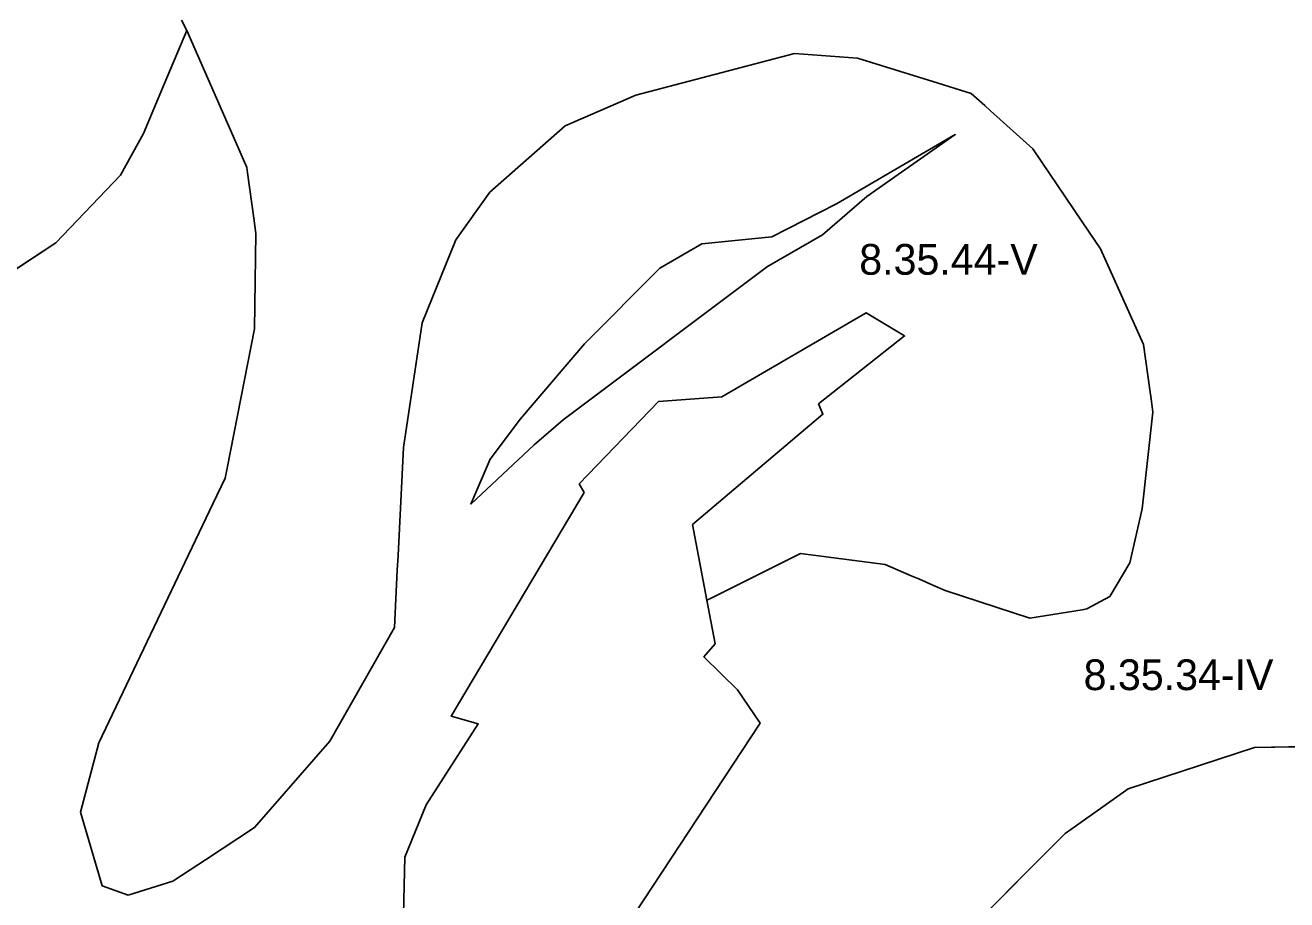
# Model space of a CAD drawing. Extents: x -547623 to -533936, y -1096714 to -1086523.
# Drawn here: x -544374 to -543964, y -1094794 to -1094509.8 of the extents above; entities that cross this region are included whole.
import ezdxf

# ---------------------------------------------------------------- set-up
doc = ezdxf.new("R2010")
doc.units = 0
doc.layers.add('Vrstva 27', color=7, linetype='Continuous')
doc.layers.add('Vrstva 28', color=7, linetype='Continuous')

msp = doc.modelspace()

# ---------------------------------------------------------------- linework, layer by layer
at = {"layer": 'Vrstva 28'}
for p, q in [((-544328.81, -1094529), (-544321.5, -1094511.5)), ((-544321.5, -1094511.5), (-544328.81, -1094529)), ((-544321.5, -1094511.5), (-544328.81, -1094529)), ((-544321.5, -1094511.5), (-544323.2, -1094508.1)), ((-544323.2, -1094508.1), (-544321.5, -1094511.5)), ((-544323.2, -1094508.1), (-544321.5, -1094511.5)), ((-544304.91, -1094549.36), (-544321.5, -1094511.5)), ((-544321.5, -1094511.5), (-544304.91, -1094549.36)), ((-544304.91, -1094549.36), (-544321.5, -1094511.5)), ((-544321.5, -1094511.5), (-544304.91, -1094549.36)), ((-544124, -1094519), (-544175.5, -1094532.5)), ((-544175.5, -1094532.5), (-544124, -1094519)), ((-544124, -1094519), (-544175.5, -1094532.5)), ((-544175.5, -1094532.5), (-544124, -1094519)), ((-544103.5, -1094520.5), (-544124, -1094519)), ((-544124, -1094519), (-544103.5, -1094520.5)), ((-544103.5, -1094520.5), (-544124, -1094519)), ((-544124, -1094519), (-544103.5, -1094520.5)), ((-544079.02, -1094528.11), (-544103.5, -1094520.5)), ((-544103.5, -1094520.5), (-544079.02, -1094528.11)), ((-544079.02, -1094528.11), (-544103.5, -1094520.5)), ((-544103.5, -1094520.5), (-544079.02, -1094528.11)), ((-544066.5, -1094532), (-544079.02, -1094528.11)), ((-544079.02, -1094528.11), (-544066.5, -1094532)), ((-544066.5, -1094532), (-544079.02, -1094528.11)), ((-544079.02, -1094528.11), (-544066.5, -1094532)), ((-544335.5, -1094545), (-544328.81, -1094529)), ((-544328.81, -1094529), (-544335.5, -1094545)), ((-544328.81, -1094529), (-544335.5, -1094545)), ((-544175.5, -1094532.5), (-544198.5, -1094542.5)), ((-544198.5, -1094542.5), (-544175.5, -1094532.5)), ((-544175.5, -1094532.5), (-544198.5, -1094542.5)), ((-544198.5, -1094542.5), (-544175.5, -1094532.5)), ((-544062.13, -1094535.93), (-544066.5, -1094532)), ((-544066.5, -1094532), (-544062.13, -1094535.93)), ((-544062.13, -1094535.93), (-544066.5, -1094532)), ((-544066.5, -1094532), (-544062.13, -1094535.93)), ((-544060.29, -1094537.59), (-544062.13, -1094535.93)), ((-544062.13, -1094535.93), (-544060.29, -1094537.59)), ((-544060.29, -1094537.59), (-544062.13, -1094535.93)), ((-544062.13, -1094535.93), (-544060.29, -1094537.59)), ((-544046.5, -1094550), (-544060.29, -1094537.59)), ((-544060.29, -1094537.59), (-544046.5, -1094550)), ((-544046.5, -1094550), (-544060.29, -1094537.59)), ((-544060.29, -1094537.59), (-544046.5, -1094550)), ((-544198.5, -1094542.5), (-544223, -1094564)), ((-544223, -1094564), (-544198.5, -1094542.5)), ((-544198.5, -1094542.5), (-544223, -1094564)), ((-544223, -1094564), (-544198.5, -1094542.5)), ((-544343, -1094558.5), (-544335.5, -1094545)), ((-544335.5, -1094545), (-544343, -1094558.5)), ((-544335.5, -1094545), (-544343, -1094558.5)), ((-544302, -1094556), (-544304.91, -1094549.36)), ((-544304.91, -1094549.36), (-544302, -1094556)), ((-544302, -1094556), (-544304.91, -1094549.36)), ((-544304.91, -1094549.36), (-544302, -1094556)), ((-544030.47, -1094573.68), (-544046.5, -1094550)), ((-544046.5, -1094550), (-544030.47, -1094573.68)), ((-544030.47, -1094573.68), (-544046.5, -1094550)), ((-544046.5, -1094550), (-544030.47, -1094573.68)), ((-544301.75, -1094557.82), (-544302, -1094556)), ((-544302, -1094556), (-544301.75, -1094557.82)), ((-544301.75, -1094557.82), (-544302, -1094556)), ((-544302, -1094556), (-544301.75, -1094557.82)), ((-544364, -1094580.5), (-544343, -1094558.5)), ((-544343, -1094558.5), (-544364, -1094580.5)), ((-544343, -1094558.5), (-544364, -1094580.5)), ((-544299.69, -1094572.52), (-544301.75, -1094557.82)), ((-544301.75, -1094557.82), (-544299.69, -1094572.52)), ((-544299.69, -1094572.52), (-544301.75, -1094557.82)), ((-544301.75, -1094557.82), (-544299.69, -1094572.52)), ((-544223, -1094564), (-544234, -1094579.5)), ((-544234, -1094579.5), (-544223, -1094564)), ((-544223, -1094564), (-544234, -1094579.5)), ((-544234, -1094579.5), (-544223, -1094564)), ((-544299, -1094577.5), (-544299.69, -1094572.52)), ((-544299.69, -1094572.52), (-544299, -1094577.5)), ((-544299, -1094577.5), (-544299.69, -1094572.52)), ((-544299.69, -1094572.52), (-544299, -1094577.5)), ((-544299.5, -1094608.5), (-544299, -1094577.5)), ((-544299, -1094577.5), (-544299.5, -1094608.5)), ((-544299.5, -1094608.5), (-544299, -1094577.5)), ((-544299, -1094577.5), (-544299.5, -1094608.5)), ((-544024.5, -1094582.5), (-544030.47, -1094573.68)), ((-544030.47, -1094573.68), (-544024.5, -1094582.5)), ((-544024.5, -1094582.5), (-544030.47, -1094573.68)), ((-544030.47, -1094573.68), (-544024.5, -1094582.5)), ((-544400.5, -1094604.5), (-544364, -1094580.5)), ((-544364, -1094580.5), (-544400.5, -1094604.5)), ((-544364, -1094580.5), (-544400.5, -1094604.5)), ((-544234, -1094579.5), (-544245, -1094606.5)), ((-544245, -1094606.5), (-544234, -1094579.5)), ((-544234, -1094579.5), (-544245, -1094606.5)), ((-544245, -1094606.5), (-544234, -1094579.5)), ((-544010.5, -1094613.5), (-544024.5, -1094582.5)), ((-544024.5, -1094582.5), (-544010.5, -1094613.5)), ((-544010.5, -1094613.5), (-544024.5, -1094582.5)), ((-544024.5, -1094582.5), (-544010.5, -1094613.5)), ((-544308.36, -1094653.71), (-544299.5, -1094608.5)), ((-544299.5, -1094608.5), (-544308.36, -1094653.71)), ((-544308.36, -1094653.71), (-544299.5, -1094608.5)), ((-544299.5, -1094608.5), (-544308.36, -1094653.71)), ((-544245, -1094606.5), (-544251, -1094647)), ((-544251, -1094647), (-544245, -1094606.5)), ((-544245, -1094606.5), (-544251, -1094647)), ((-544251, -1094647), (-544245, -1094606.5)), ((-544008.48, -1094628.3), (-544010.5, -1094613.5)), ((-544010.5, -1094613.5), (-544008.48, -1094628.3)), ((-544008.48, -1094628.3), (-544010.5, -1094613.5)), ((-544010.5, -1094613.5), (-544008.48, -1094628.3)), ((-544008.08, -1094631.23), (-544008.48, -1094628.3)), ((-544008.48, -1094628.3), (-544008.08, -1094631.23)), ((-544008.08, -1094631.23), (-544008.48, -1094628.3)), ((-544008.48, -1094628.3), (-544008.08, -1094631.23)), ((-544007.5, -1094635.5), (-544008.08, -1094631.23)), ((-544008.08, -1094631.23), (-544007.5, -1094635.5)), ((-544007.5, -1094635.5), (-544008.08, -1094631.23)), ((-544008.08, -1094631.23), (-544007.5, -1094635.5)), ((-544011, -1094667), (-544007.5, -1094635.5)), ((-544007.5, -1094635.5), (-544011, -1094667)), ((-544011, -1094667), (-544007.5, -1094635.5)), ((-544007.5, -1094635.5), (-544011, -1094667)), ((-544251, -1094647), (-544252.8, -1094682.13)), ((-544252.8, -1094682.13), (-544251, -1094647)), ((-544251, -1094647), (-544252.8, -1094682.13)), ((-544252.8, -1094682.13), (-544251, -1094647)), ((-544309, -1094657), (-544308.36, -1094653.71)), ((-544308.36, -1094653.71), (-544309, -1094657)), ((-544309, -1094657), (-544308.36, -1094653.71)), ((-544308.36, -1094653.71), (-544309, -1094657)), ((-544312.98, -1094665.36), (-544309, -1094657)), ((-544309, -1094657), (-544312.98, -1094665.36)), ((-544312.98, -1094665.36), (-544309, -1094657)), ((-544309, -1094657), (-544312.98, -1094665.36)), ((-544193.94, -1094658.82), (-544192.3, -1094661.6)), ((-544350, -1094743), (-544312.98, -1094665.36)), ((-544312.98, -1094665.36), (-544350, -1094743)), ((-544350, -1094743), (-544312.98, -1094665.36)), ((-544312.98, -1094665.36), (-544350, -1094743)), ((-544015, -1094684.5), (-544011, -1094667)), ((-544011, -1094667), (-544015, -1094684.5)), ((-544015, -1094684.5), (-544011, -1094667)), ((-544011, -1094667), (-544015, -1094684.5)), ((-544252.8, -1094682.13), (-544253.04, -1094686.84)), ((-544253.04, -1094686.84), (-544252.8, -1094682.13)), ((-544252.8, -1094682.13), (-544253.04, -1094686.84)), ((-544253.04, -1094686.84), (-544252.8, -1094682.13)), ((-544151, -1094696), (-544122, -1094681.5)), ((-544122, -1094681.5), (-544151, -1094696)), ((-544151, -1094696), (-544122, -1094681.5)), ((-544122, -1094681.5), (-544151, -1094696)), ((-544122, -1094681.5), (-544094.5, -1094685)), ((-544094.5, -1094685), (-544122, -1094681.5)), ((-544122, -1094681.5), (-544094.5, -1094685)), ((-544094.5, -1094685), (-544122, -1094681.5)), ((-544253.04, -1094686.84), (-544254, -1094705.5)), ((-544254, -1094705.5), (-544253.04, -1094686.84)), ((-544253.04, -1094686.84), (-544254, -1094705.5)), ((-544254, -1094705.5), (-544253.04, -1094686.84)), ((-544094.5, -1094685), (-544086.02, -1094688.69)), ((-544086.02, -1094688.69), (-544094.5, -1094685)), ((-544094.5, -1094685), (-544086.02, -1094688.69)), ((-544086.02, -1094688.69), (-544094.5, -1094685)), ((-544021.5, -1094695.5), (-544015, -1094684.5)), ((-544015, -1094684.5), (-544021.5, -1094695.5)), ((-544021.5, -1094695.5), (-544015, -1094684.5)), ((-544015, -1094684.5), (-544021.5, -1094695.5)), ((-544086.02, -1094688.69), (-544083.39, -1094689.84)), ((-544083.39, -1094689.84), (-544086.02, -1094688.69)), ((-544086.02, -1094688.69), (-544083.39, -1094689.84)), ((-544083.39, -1094689.84), (-544086.02, -1094688.69)), ((-544083.39, -1094689.84), (-544079.02, -1094691.75)), ((-544079.02, -1094691.75), (-544083.39, -1094689.84)), ((-544083.39, -1094689.84), (-544079.02, -1094691.75)), ((-544079.02, -1094691.75), (-544083.39, -1094689.84)), ((-544079.02, -1094691.75), (-544075, -1094693.5)), ((-544075, -1094693.5), (-544079.02, -1094691.75)), ((-544079.02, -1094691.75), (-544075, -1094693.5)), ((-544075, -1094693.5), (-544079.02, -1094691.75)), ((-544152.47, -1094696.69), (-544151, -1094696)), ((-544151, -1094696), (-544152.47, -1094696.69)), ((-544152.47, -1094696.69), (-544151, -1094696)), ((-544151, -1094696), (-544152.47, -1094696.69)), ((-544075, -1094693.5), (-544047.5, -1094702.5)), ((-544047.5, -1094702.5), (-544075, -1094693.5)), ((-544075, -1094693.5), (-544047.5, -1094702.5)), ((-544047.5, -1094702.5), (-544075, -1094693.5)), ((-544029, -1094699.5), (-544021.5, -1094695.5)), ((-544021.5, -1094695.5), (-544029, -1094699.5)), ((-544029, -1094699.5), (-544021.5, -1094695.5)), ((-544021.5, -1094695.5), (-544029, -1094699.5)), ((-544047.5, -1094702.5), (-544030.47, -1094699.74)), ((-544030.47, -1094699.74), (-544047.5, -1094702.5)), ((-544047.5, -1094702.5), (-544030.47, -1094699.74)), ((-544030.47, -1094699.74), (-544047.5, -1094702.5)), ((-544030.47, -1094699.74), (-544029, -1094699.5)), ((-544029, -1094699.5), (-544030.47, -1094699.74)), ((-544030.47, -1094699.74), (-544029, -1094699.5)), ((-544029, -1094699.5), (-544030.47, -1094699.74)), ((-544254, -1094705.5), (-544275, -1094742.5)), ((-544275, -1094742.5), (-544254, -1094705.5)), ((-544254, -1094705.5), (-544275, -1094742.5)), ((-544275, -1094742.5), (-544254, -1094705.5)), ((-544356, -1094765.5), (-544350, -1094743)), ((-544350, -1094743), (-544356, -1094765.5)), ((-544356, -1094765.5), (-544350, -1094743)), ((-544350, -1094743), (-544356, -1094765.5)), ((-544275, -1094742.5), (-544299.5, -1094770.5)), ((-544299.5, -1094770.5), (-544275, -1094742.5)), ((-544275, -1094742.5), (-544299.5, -1094770.5)), ((-544299.5, -1094770.5), (-544275, -1094742.5)), ((-543974.5, -1094744.5), (-544015.5, -1094758)), ((-544015.5, -1094758), (-543974.5, -1094744.5)), ((-544015.5, -1094758), (-543974.5, -1094744.5)), ((-543947, -1094744), (-543974.5, -1094744.5)), ((-543974.5, -1094744.5), (-543947, -1094744)), ((-543974.5, -1094744.5), (-543947, -1094744)), ((-544015.5, -1094758), (-544030.47, -1094768.59)), ((-544030.47, -1094768.59), (-544015.5, -1094758)), ((-544030.47, -1094768.59), (-544015.5, -1094758)), ((-544349, -1094789.5), (-544356, -1094765.5)), ((-544356, -1094765.5), (-544349, -1094789.5)), ((-544349, -1094789.5), (-544356, -1094765.5)), ((-544356, -1094765.5), (-544349, -1094789.5)), ((-544030.47, -1094768.59), (-544036, -1094772.5)), ((-544036, -1094772.5), (-544030.47, -1094768.59)), ((-544036, -1094772.5), (-544030.47, -1094768.59)), ((-544299.5, -1094770.5), (-544315.42, -1094781.01)), ((-544315.42, -1094781.01), (-544299.5, -1094770.5)), ((-544299.5, -1094770.5), (-544315.42, -1094781.01)), ((-544315.42, -1094781.01), (-544299.5, -1094770.5)), ((-544036, -1094772.5), (-544074.5, -1094811)), ((-544074.5, -1094811), (-544036, -1094772.5)), ((-544074.5, -1094811), (-544036, -1094772.5)), ((-544315.42, -1094781.01), (-544325.32, -1094787.55)), ((-544325.32, -1094787.55), (-544315.42, -1094781.01)), ((-544315.42, -1094781.01), (-544325.32, -1094787.55)), ((-544325.32, -1094787.55), (-544315.42, -1094781.01)), ((-544340.5, -1094792.5), (-544349, -1094789.5)), ((-544349, -1094789.5), (-544340.5, -1094792.5)), ((-544340.5, -1094792.5), (-544349, -1094789.5)), ((-544349, -1094789.5), (-544340.5, -1094792.5)), ((-544326, -1094788), (-544340.5, -1094792.5)), ((-544340.5, -1094792.5), (-544326, -1094788)), ((-544326, -1094788), (-544340.5, -1094792.5)), ((-544340.5, -1094792.5), (-544326, -1094788)), ((-544325.32, -1094787.55), (-544326, -1094788)), ((-544326, -1094788), (-544325.32, -1094787.55)), ((-544325.32, -1094787.55), (-544326, -1094788)), ((-544326, -1094788), (-544325.32, -1094787.55))]:
    msp.add_line(p, q, dxfattribs=at)
for points in [[(-544400.5, -1094604.5), (-544364, -1094580.5), (-544343, -1094558.5), (-544335.5, -1094545), (-544328.81, -1094529), (-544321.5, -1094511.5), (-544323.2, -1094508.1)], [(-544199.13, -1094638.07), (-544132.76, -1094588.23), (-544114.86, -1094577.94), (-544100.48, -1094565.45), (-544071.7, -1094545.35), (-544110.29, -1094567.86), (-544131.33, -1094578.56), (-544154.13, -1094580.86), (-544167.71, -1094588.79), (-544192.23, -1094613.37), (-544212.96, -1094637.68), (-544222.92, -1094650.8), (-544229.14, -1094665.39), (-544208.52, -1094646.16), (-544199.13, -1094638.07)], [(-544116.16, -1094632.86), (-544088.17, -1094610.74), (-544100.7, -1094603.24), (-544147.59, -1094630.56), (-544168.14, -1094632.05), (-544193.94, -1094658.82)], [(-544152.47, -1094696.69), (-544157.16, -1094672.05), (-544114.71, -1094636.22), (-544116.16, -1094632.86)], [(-544192.3, -1094661.6), (-544235.5, -1094734.38), (-544226.72, -1094736.83), (-544243.64, -1094763.14), (-544250.63, -1094780.14), (-544250.99, -1094798.8), (-544243.83, -1094800.64), (-544273.71, -1094846.38), (-544259.43, -1094843.38), (-544268.47, -1094863.51), (-544271.66, -1094871.08), (-544256.99, -1094857.96), (-544237.03, -1094843.29), (-544198.14, -1094819.57), (-544180.29, -1094805.17), (-544178.81, -1094802.92), (-544135.15, -1094736.61), (-544142.48, -1094725.77), (-544153.43, -1094715.06), (-544149.79, -1094710.8), (-544152.47, -1094696.69), (-544152.47, -1094696.69)], [(-543947, -1094744), (-543974.5, -1094744.5), (-544015.5, -1094758), (-544030.47, -1094768.59), (-544036, -1094772.5), (-544074.5, -1094811)]]:
    msp.add_lwpolyline(points, dxfattribs=at)

# ---------------------------------------------------------------- texts
at = {"layer": 'Vrstva 27'}
for s, p in [('8.35.44-V', (-544102.92, -1094590.88)), ('8.35.34-IV', (-544030.01, -1094725.87))]:
    msp.add_text(s, height=10, dxfattribs=at).set_placement(p)

doc.saveas('drawing.dxf')
